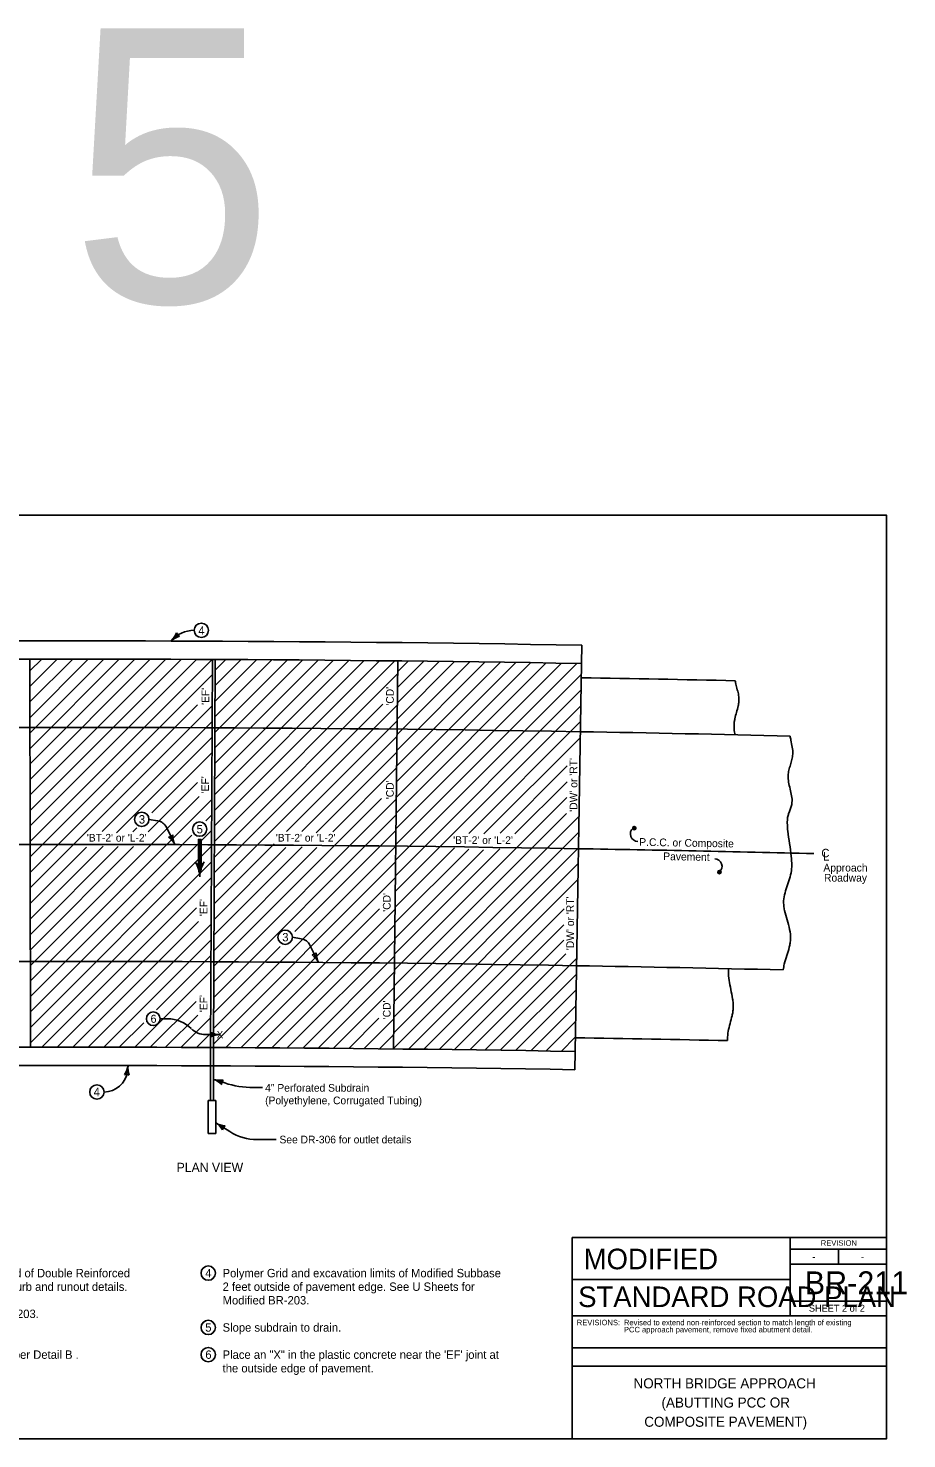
# Model space of a CAD drawing. Extents: x 10130 to 81668, y 5440 to 21644.
# Drawn here: x 25789 to 27712, y 7924 to 11009 of the extents above; entities that cross this region are included whole.
import ezdxf

# ---------------------------------------------------------------- set-up
doc = ezdxf.new("R2010")
doc.units = 0
for name, color, linetype in [('Default', 7, 'Continuous'), ('dsnStdBlockModified', 7, 'Continuous'), ('dsnStdBlockNotModified', 7, 'Continuous'), ('dsnStdBorder', 7, 'Continuous'), ('dsnStdLabel', 7, 'Continuous'), ('dsnstdModifiedBlock', 7, 'Continuous'), ('Level 1', 7, 'Continuous'), ('SheetBorder', 7, 'Continuous'), ('SheetText', 7, 'Continuous')]:
    doc.layers.add(name, color=color, linetype=linetype)

msp = doc.modelspace()

# ---------------------------------------------------------------- linework, layer by layer
at = {"layer": 'Default'}
for p, q in [((27000.2, 9619.8), (27000.8, 9659.8)), ((26985.7, 8771.3), (26985.1, 8731.3))]:
    msp.add_line(p, q, dxfattribs=at)
for radius, end in [(65123.7, 90.60898), (64195, 90.563142)]:
    msp.add_arc((25894.2, -55454.5), radius, 89.026299, end, dxfattribs=at)
for points in [[(27336.5, 9582), (27337.1, 9577.8), (27340.1, 9565.4), (27343.2, 9553.1), (27344.3, 9547), (27344.5, 9543.9), (27344.5, 9540.8), (27344.1, 9533.7), (27342.8, 9526.8), (27339.2, 9512.8), (27335.5, 9498.8), (27334.2, 9491.8), (27333.8, 9488.3), (27333.7, 9484.7), (27334.8, 9469.7), (27335.9, 9463.9)], [(27456.5, 9461.1), (27458.3, 9451.8), (27461.2, 9436.7), (27462.2, 9421.6), (27460.5, 9409.8), (27457.2, 9398.1), (27453.9, 9386.4), (27452.1, 9374.7), (27453.2, 9360), (27456.4, 9345.2), (27459.7, 9330.4), (27460.6, 9315.7), (27458.9, 9306.8), (27455.7, 9298.1), (27452.6, 9289.4), (27450.7, 9280.5), (27450.5, 9267), (27451.4, 9253.3), (27455.2, 9225.8), (27459, 9198.3), (27460.1, 9177.9), (27459.8, 9171.1), (27456.6, 9153.4), (27451, 9135.8), (27445.4, 9118.3), (27442.3, 9100.6), (27442.6, 9090.2), (27444.2, 9079.7), (27449.8, 9058.9), (27455.4, 9038.1), (27457.6, 9017.4), (27456.6, 9008.2), (27454.7, 8999), (27449.2, 8980.7), (27443.7, 8962.3), (27441.4, 8949.5)], [(27321.7, 8952.3), (27321.4, 8946.6), (27322.9, 8926.7), (27326.8, 8906.6), (27330.5, 8886.5), (27331.3, 8881.6), (27331.8, 8876.6), (27331.9, 8871.6), (27331.8, 8866.6), (27331.1, 8857.9), (27329.5, 8849.4), (27325.2, 8832.3), (27321.1, 8815.2), (27319.5, 8797.9), (27319.6, 8794.8)]]:
    msp.add_spline(points, degree=3, dxfattribs=at)
at = {"layer": 'dsnStdBlockModified'}
for p, q in [((26053.1, 9278.8), (26072.6, 9275.5)), ((26091.4, 9261.5), (26110.1, 9223.7)), ((26367.1, 9021), (26386.6, 9017.8)), ((26405.4, 9003.8), (26424, 8965.9)), ((26093.9, 8842.6), (26077.6, 8842.6)), ((26208.4, 8808), (26177.2, 8808)), ((26005.9, 8727.4), (26007.6, 8740.5)), ((26301.6, 8692.3), (26282, 8692.3)), ((26230.1, 8595.8), (26199.5, 8614.9)), ((26331.7, 8578.5), (26290.1, 8578.5))]:
    msp.add_line(p, q, dxfattribs=at)
for centre, radius, start, end in [((26152.2, 9625.5), 66.8, 90, 139.4393), ((26068.4, 9250.2), 25.7, 26.2458, 80.4677), ((27123.4, 9247.1), 16.5, 130.2796, 268.9704), ((27291.1, 9176.2), 16.5, 310.2794, 88.9704), ((26382.3, 8992.4), 25.7, 26.2458, 80.4677), ((26093.9, 8769.2), 73.4, 45, 90), ((26177.2, 8852.1), 44.1, 225, 270), ((25954.9, 8733.9), 51.4, 270, 352.7713), ((26282, 8897.9), 205.6, 252.1406, 270), ((26290.1, 8691.6), 113.1, 237.9168, 270)]:
    msp.add_arc(centre, radius, start, end, dxfattribs=at)
at = {"layer": 'dsnStdBorder'}
for p, q in [((25792.7, 9603.4), (25818.6, 9629.2)), ((25792.8, 9535.6), (25886.5, 9629.2)), ((25792.8, 9569.5), (25852.5, 9629.2)), ((25792.9, 9501.7), (25920.4, 9629.2)), ((25793, 9433.9), (25988.2, 9629.2)), ((25793, 9467.8), (25954.3, 9629.2)), ((25793.1, 9400), (26022.1, 9629.1)), ((25793.1, 9366.2), (26056, 9629)), ((25793.2, 9332.3), (26089.8, 9628.9)), ((25793.2, 9298.4), (26123.7, 9628.8)), ((25793.3, 9264.5), (26157.5, 9628.7)), ((25793.3, 9230.6), (26191.3, 9628.6)), ((26196.6, 9264.4), (26558, 9625.9)), ((26196.8, 9298.5), (26524.4, 9626.2)), ((26196.9, 9332.6), (26490.8, 9626.5)), ((26197.1, 9366.7), (26457.2, 9626.8)), ((26197.2, 9400.8), (26423.5, 9627.1)), ((26197.4, 9434.9), (26389.8, 9627.4)), ((26197.5, 9469), (26356.1, 9627.6)), ((26197.7, 9503.1), (26322.4, 9627.8)), ((26197.9, 9537.2), (26288.7, 9628)), ((26198, 9571.3), (26255, 9628.2)), ((26198.2, 9605.4), (26221.2, 9628.4)), ((25793.4, 9196.7), (26192, 9595.3)), ((26196.3, 9196.2), (26597.4, 9597.3)), ((26196.4, 9230.3), (26591.6, 9625.5)), ((26593, 9189.5), (26999.8, 9596.3)), ((26593.4, 9223.8), (26989.5, 9620)), ((26593.7, 9258.2), (26956.1, 9620.6)), ((26594.1, 9292.5), (26922.7, 9621.1)), ((26594.5, 9326.8), (26889.3, 9621.6)), ((26594.8, 9361.1), (26855.9, 9622.1)), ((26595.2, 9395.4), (26822.4, 9622.6)), ((26595.6, 9429.7), (26789, 9623.1)), ((26596, 9464), (26755.5, 9623.5)), ((26596.3, 9498.3), (26722, 9624)), ((26596.7, 9532.7), (26688.4, 9624.4)), ((26597.1, 9567), (26654.9, 9624.8)), ((26597.4, 9601.3), (26621.3, 9625.2)), ((26592.6, 9155.2), (26999.2, 9561.8)), ((25793.4, 9162.8), (26159.6, 9529)), ((25793.5, 9128.9), (26191.6, 9527.1)), ((26196, 9128), (26596.7, 9528.7)), ((26196.1, 9162.1), (26565, 9531)), ((26592.2, 9120.9), (26998.6, 9527.3)), ((25950.6, 9252.2), (26191.5, 9493)), ((26354, 9252.1), (26596.3, 9494.4)), ((26753.5, 9248.2), (26998, 9492.7)), ((25981.8, 9249.4), (26191.3, 9458.9)), ((26388, 9252.1), (26595.9, 9460.1)), ((26786.1, 9246.9), (26997.4, 9458.2)), ((26059.4, 9293.1), (26191.2, 9424.8)), ((26419.3, 9249.5), (26595.5, 9425.8)), ((26455.3, 9251.6), (26595.2, 9391.5)), ((26821.8, 9248.6), (26968.8, 9395.6)), ((26051.8, 9251.5), (26159.5, 9359.2)), ((26854.2, 9247.1), (26968.3, 9361.2)), ((25793.7, 8959.5), (26162.8, 9328.6)), ((25793.8, 8925.6), (26190.7, 9322.5)), ((26195, 8923.4), (26594.4, 9322.8)), ((26195.2, 8957.5), (26562.5, 9324.8)), ((26590.4, 8949.4), (26967.5, 9326.4)), ((26177.9, 9275.8), (26190.5, 9288.4)), ((26194.9, 8889.3), (26594.1, 9288.5)), ((26590, 8915), (26966.9, 9291.9)), ((26018.1, 9251.7), (26026.4, 9260.1)), ((26589.6, 8880.7), (26994.5, 9285.6)), ((25793.8, 8891.7), (26146.7, 9244.6)), ((25793.9, 8857.8), (26190.4, 9254.3)), ((26164.4, 9180.6), (26164.4, 9235.1)), ((26195.8, 9093.9), (26327, 9225.1)), ((26372.8, 9033.3), (26593.7, 9254.2)), ((26589.3, 8846.4), (26993.9, 9251)), ((25793.5, 9095.1), (25916.7, 9218.2)), ((25793.6, 9061.2), (25952.9, 9220.4)), ((25793.6, 9027.3), (25985.5, 9219.1)), ((25793.7, 8993.4), (26019.4, 9219.1)), ((25794, 8823.9), (26190.2, 9220.2)), ((26194.5, 8821.1), (26593.3, 9219.9)), ((26195.3, 8991.6), (26420.7, 9217)), ((26195.5, 9025.7), (26388.2, 9218.4)), ((26195.6, 9059.8), (26352.8, 9217)), ((26588.9, 8812.1), (26993.3, 9216.5)), ((26590.8, 8983.7), (26821.2, 9214.1)), ((26591.1, 9018), (26785.4, 9212.3)), ((26591.5, 9052.3), (26753.1, 9213.8)), ((26591.9, 9086.6), (26721.7, 9216.4)), ((25794, 8790.1), (26190.1, 9186.1)), ((26161.3, 9180.7), (26161.3, 9180.7)), ((26167.7, 9180.8), (26167.7, 9180.8)), ((26194.4, 8787), (26592.9, 9185.6)), ((26588.5, 8777.8), (26992.7, 9182)), ((25818.4, 8780.5), (26189.9, 9152)), ((26221.1, 8779.8), (26592.6, 9151.3)), ((26621.2, 8776.5), (26992.1, 9147.5)), ((25852.4, 8780.6), (26157.2, 9085.4)), ((26254.8, 8779.6), (26558.1, 9082.8)), ((26288.6, 8779.4), (26591.8, 9082.6)), ((26654.7, 8776.1), (26961.7, 9083.1)), ((25886.4, 8780.6), (26161.5, 9055.7)), ((25920.3, 8780.6), (26189.4, 9049.7)), ((26322.3, 8779.2), (26591.5, 9048.3)), ((26688.2, 8775.7), (26960.9, 9048.3)), ((25954.2, 8780.6), (26189.3, 9015.6)), ((26356, 8778.9), (26591.1, 9014)), ((26721.8, 8775.3), (26961.3, 9014.8)), ((26069.5, 8861.9), (26189.1, 8981.5)), ((26194.7, 8855.2), (26340.1, 9000.6)), ((26389.7, 8778.7), (26590.7, 8979.7)), ((26755.3, 8774.8), (26965.3, 8984.9)), ((26022, 8780.5), (26189, 8947.4)), ((26788.7, 8774.4), (26989.2, 8974.8)), ((26423.4, 8778.4), (26590.3, 8945.4)), ((26822.2, 8773.9), (26988.6, 8940.3)), ((26457, 8778.1), (26590, 8911.1)), ((26855.7, 8773.4), (26988, 8905.8)), ((26055.9, 8780.4), (26156.2, 8880.7)), ((26889.1, 8772.9), (26987.4, 8871.2)), ((25988.1, 8780.5), (26041.7, 8834.1)), ((26089.7, 8780.3), (26160, 8850.6)), ((26123.5, 8780.2), (26188.5, 8845.1)), ((26490.6, 8777.8), (26556.6, 8843.8)), ((26524.3, 8777.5), (26589.2, 8842.5)), ((26922.5, 8772.4), (26986.9, 8836.7)), ((26157.3, 8780), (26188.3, 8811)), ((26557.9, 8777.2), (26588.9, 8808.1)), ((26955.9, 8771.8), (26986.3, 8802.2)), ((26188.2, 8779.9), (26188.2, 8664.2)), ((26194.4, 8779.9), (26194.4, 8664.2)), ((26218.9, 8702.2), (26194.4, 8710.2)), ((26194.4, 8710.2), (26213.2, 8704.1)), ((26183, 8664.2), (26199.5, 8664.2)), ((26183, 8664.2), (26183, 8591.8)), ((26199.5, 8664.2), (26199.5, 8591.8)), ((26199.5, 8614.9), (26216.2, 8604.4)), ((26183, 8591.8), (26199.5, 8591.8))]:
    msp.add_line(p, q, dxfattribs=at)
msp.add_lwpolyline([(24968.4, 9591.4), (25065.1, 9592.8), (25143.6, 9606.4), (25183, 9607), (25202.6, 9610.6), (25202.4, 9625.6), (25553.2, 9628.3), (25792.7, 9629.2), (25794, 8780.5), (25396.8, 8778.7), (25262.8, 8777.5), (25262.8, 8777.5), (25262.6, 8792.5), (25242.9, 8795.5), (25203.5, 8794.9), (25124.6, 8806.2), (25027.9, 8804.9)], close=True, dxfattribs=at)
for points in [[(27115.1, 9256.4), (27116.4, 9256.9), (27118.3, 9257.4), (27118.7, 9259.3), (27118.5, 9261), (27117.3, 9262.6), (27115.5, 9262.5), (27113.6, 9262.3), (27112.6, 9260.8), (27112.4, 9259.2), (27113.5, 9257.1), (27114.9, 9256.9), (27116.8, 9257.3), (27118.4, 9258.5), (27118.4, 9260.3), (27117.2, 9261.8), (27115.5, 9262), (27113.6, 9261.6), (27113.2, 9260.6), (27112.8, 9259.3), (27113.7, 9257.7), (27115.1, 9257.7), (27116.7, 9257.9), (27117.8, 9258.8), (27117.3, 9260.4), (27116.1, 9261.3), (27114.5, 9261.4), (27114.1, 9260.6), (27113.6, 9259.6), (27114.3, 9258.3), (27115.5, 9258), (27116.6, 9258.6), (27116.7, 9259.8), (27116.1, 9260.6), (27115.1, 9260.9), (27114.5, 9260.5), (27114.2, 9259.8), (27114.8, 9258.9), (27115.5, 9258.7), (27116.2, 9259.1), (27116.1, 9259.8), (27115.6, 9260.2), (27114.9, 9260.2), (27114.9, 9259.6), (27115.5, 9259.3)], [(26167.4, 9180.7), (26167.4, 9235.1), (26161.3, 9235.1), (26161.3, 9180.7), (26166.6, 9180.9), (26166.8, 9234.4), (26161.9, 9234.3), (26162.1, 9181.9), (26165.7, 9181.8), (26165.9, 9233.7), (26162.7, 9233.5), (26162.7, 9182.6), (26165, 9182.4), (26165.3, 9233.1), (26163.4, 9233), (26163.5, 9183.3)], [(26171.5, 9182.2), (26167.8, 9179.8), (26162.4, 9179.6), (26157.7, 9181.6), (26161, 9173.5), (26163.8, 9164.1), (26164.4, 9161.5), (26165.7, 9168.3), (26169.1, 9178.1), (26170.7, 9181.1), (26159.3, 9180), (26164.2, 9165.5), (26168.5, 9179.6), (26160.6, 9179.1), (26164.2, 9169.1), (26166.5, 9178.3), (26161.9, 9178.7), (26164, 9172.4), (26165.3, 9177.2), (26163.1, 9177.5), (26163.8, 9175.1)], [(27301.4, 9160.3), (27302.7, 9160.8), (27304.6, 9161.3), (27305, 9163.3), (27304.7, 9165), (27303.6, 9166.5), (27301.8, 9166.4), (27299.8, 9166.2), (27298.9, 9164.7), (27298.7, 9163.1), (27299.8, 9161), (27301.2, 9160.8), (27303.1, 9161.2), (27304.7, 9162.4), (27304.6, 9164.2), (27303.5, 9165.7), (27301.8, 9165.9), (27299.8, 9165.5), (27299.5, 9164.5), (27299.1, 9163.2), (27300, 9161.6), (27301.4, 9161.6), (27303, 9161.9), (27304.1, 9162.7), (27303.6, 9164.3), (27302.4, 9165.3), (27300.8, 9165.3), (27300.4, 9164.5), (27299.9, 9163.5), (27300.6, 9162.3), (27301.8, 9162), (27302.9, 9162.5), (27302.9, 9163.7), (27302.4, 9164.5), (27301.3, 9164.8), (27300.8, 9164.4), (27300.5, 9163.7), (27301, 9162.8), (27301.8, 9162.6), (27302.5, 9163), (27302.4, 9163.7), (27301.9, 9164.1), (27301.1, 9164.1), (27301.1, 9163.5), (27301.8, 9163.2)], [(26213.9, 8707.7), (26212.1, 8704.4), (26211.7, 8700.7), (26208.1, 8704.1), (26201.9, 8707.7), (26209.6, 8707.1), (26213.2, 8707.5), (26211.4, 8704.6), (26211, 8702.3), (26208.6, 8704.5), (26205.2, 8706.6), (26209.5, 8706.5), (26211.8, 8706.6), (26210.5, 8703.7), (26208.1, 8705.7), (26210.5, 8705.7), (26210.2, 8704.6), (26209.3, 8705.3)], [(26217.8, 8607.8), (26215.3, 8605), (26213.9, 8601.5), (26211.3, 8605.6), (26206.2, 8610.7), (26213.5, 8608.2), (26217.1, 8607.7), (26214.7, 8605.4), (26213.7, 8603.2), (26212, 8605.9), (26209.2, 8608.9), (26213.3, 8607.7), (26215.6, 8607.2), (26213.5, 8604.7), (26211.7, 8607.2), (26214, 8606.6), (26213.5, 8605.7), (26212.8, 8606.6)]]:
    msp.add_lwpolyline(points, dxfattribs=at)
for centre, radius in [((26167.9, 9692.3), 15.7), ((26037.4, 9278.8), 15.7), ((26164.1, 9257.4), 15.7), ((27115.5, 9259.7), 3.62), ((27301.8, 9163.6), 3.62), ((26351.3, 9021), 15.7), ((26062.5, 8842.6), 15), ((25939.2, 8682.5), 15.7), ((26182.9, 8286.4), 15.7), ((26182.9, 8167.5), 15.7), ((26182.9, 8108.1), 15.7)]:
    msp.add_circle(centre, radius, dxfattribs=at)
for centre, radius, start, end in [((26071.3, 9701.5), 44.4, 312.7719, 340.8444), ((26131.6, 9636.3), 44.4, 104.6994, 132.7719), ((26128.8, 9694.2), 17.1, 205.0386, 240.5053), ((25894.2, -55454.5), 64934.4, 89.026299, 90.808989), ((26093.6, 9257), 17.1, 278.5122, 313.9789), ((26070.3, 9204), 44.4, 26.2455, 54.318), ((26149.9, 9243.3), 44.4, 178.1731, 206.2455), ((25894.2, -55454.5), 64678.5, 88.569913, 89.026299), ((26164.4, 9191.9), 11.6, 211.7147, 328.2853), ((26098.1, 9150.9), 66.3, 1.6842, 31.7143), ((26230.6, 9150.9), 66.3, 148.2857, 178.3158), ((26407.6, 8999.3), 17.1, 278.5122, 313.9789), ((26384.2, 8946.3), 44.4, 26.2455, 54.318), ((26463.8, 8985.6), 44.4, 178.1731, 206.2455), ((25894.2, -55454.5), 64422.6, 89.026299, 90.781002), ((26173, 8808), 16.3, 342.2666, 17.7333), ((26208.4, 8850.3), 42.3, 241.9275, 270), ((26208.4, 8765.7), 42.3, 90, 118.0725), ((25963.5, 8746.1), 44.4, 324.6988, 352.7713), ((26051.6, 8734.9), 44.4, 172.7713, 200.8438), ((26002.9, 8703.6), 17.1, 65.0379, 100.5046), ((26181, 8668.6), 43.7, 44.0691, 72.1415), ((26207.8, 8751.7), 43.7, 252.1415, 280.214), ((26229.2, 8698.9), 16.9, 144.4082, 179.8749), ((26176.3, 8577.9), 43.7, 29.8434, 57.9159), ((26222.7, 8652), 43.7, 237.9159, 265.9884), ((26230.5, 8595.5), 16.9, 130.1825, 165.6492)]:
    msp.add_arc(centre, radius, start, end, dxfattribs=at)
at = {"layer": 'dsnStdLabel'}
for p, q in [((27456.6, 8364), (27456.6, 8272.7)), ((27456.6, 8339.1), (27667.5, 8339.1)), ((27562.1, 8339.1), (27562.1, 8305.9)), ((27456.6, 8305.9), (27667.5, 8305.9)), ((26979.5, 8272.7), (27456.6, 8272.7)), ((27456.6, 8272.7), (27456.6, 8192.7)), ((27667.5, 8224.9), (27456.6, 8224.9)), ((26979.5, 8192.7), (27667.5, 8192.7)), ((26979.5, 8122.7), (27667.5, 8122.7)), ((26979.5, 8082.7), (27667.5, 8082.7)), ((26979.5, 8082.7), (27667.5, 8082.7))]:
    msp.add_line(p, q, dxfattribs=at)
msp.add_lwpolyline([(26979.5, 8364), (27667.5, 8364), (27667.5, 7924), (26979.5, 7924)], close=True, dxfattribs=at)
at = {"layer": 'dsnstdModifiedBlock'}
for p, q in [((25794, 8780.5), (25792.7, 9629.2)), ((26188.2, 8779.9), (26192.1, 9628.6)), ((26194.4, 8779.9), (26198.3, 9628.5)), ((26588.5, 8776.8), (26597.7, 9625.4)), ((26985.7, 8771.3), (27000.2, 9619.8))]:
    msp.add_line(p, q, dxfattribs=at)
for radius, start, end in [(65083.7, 89.026299, 90.60898), (65052.5, 88.729583, 89.026299), (64934.4, 88.621312, 89.026299), (64678.5, 89.026299, 90.795051), (64422.6, 88.623824, 89.026299), (64265.1, 88.729039, 89.026299), (64235, 89.026299, 90.563142)]:
    msp.add_arc((25894.2, -55454.5), radius, start, end, dxfattribs=at)
at = {"layer": 'SheetBorder'}
msp.add_lwpolyline([(24532.5, 9944), (27667.5, 9944), (27667.5, 7924), (24532.5, 7924)], close=True, dxfattribs=at)

# ---------------------------------------------------------------- texts
at = {"layer": 'dsnStdBlockModified'}
for s, height, p in [('4', 18.4, (26161.2, 9682.5)), ('3', 18.4, (26031, 9269.6)), ('5', 18.4, (26157.5, 9248.2)), ("'BT-2' or 'L-2'", 16.8, (25917.2, 9230.2)), ("'BT-2' or 'L-2'", 16.8, (26330.8, 9230.2)), ("'BT-2' or 'L-2'", 16.8, (26719, 9225)), ('C', 18.5, (27524.8, 9195.8)), ('L', 18.5, (27528.7, 9188.7)), ('Approach', 16.88, (27529.3, 9164.7)), ('Roadway', 16.88, (27530.7, 9142.7)), ('3', 18.4, (26344.9, 9011.9)), ('6', 17.5, (26056.7, 8833.9)), ('X', 16, (26201.5, 8800)), ('4" Perforated Subdrain ', 16.8, (26307.5, 8683.2)), ('4', 18.4, (25932.1, 8673.3)), ('(Polyethylene, Corrugated Tubing)', 16.8, (26307.5, 8655.7)), ('See DR-306 for outlet details', 16.8, (26338.9, 8570.1)), ('Build 4 inch Sloped Curb to end of Double Reinforced', 18.375, (25428.4, 8277.2)), ('4', 18.4, (26176.4, 8277.2)), ('Polymer Grid and excavation limits of Modified Subbase', 18.375, (26214.4, 8277.2)), ('Section.  Refer to PV-102 for curb and runout details.', 18.375, (25428.4, 8247.5)), ('2 feet outside of pavement edge. See U Sheets for', 18.375, (26214.4, 8247.5)), ('See U Sheets for Modified BR-203.', 18.375, (25428.4, 8188.1)), ('Modified BR-203.', 18.375, (26214.4, 8217.8)), ('5', 18.4, (26176.4, 8158.3)), ('Slope subdrain to drain.', 18.375, (26214.4, 8158.3)), ('     Single Pour - Saw cut joint per Detail B .', 18.375, (25428.4, 8098.9)), ('6', 18.4, (26176.6, 8098.9)), ('Place an "X" in the plastic concrete near the \'EF\' joint at', 18.375, (26214.4, 8098.9)), ('the outside edge of pavement.', 18.375, (26214.4, 8069.2))]:
    msp.add_text(s, height=height, dxfattribs=at).set_placement(p)
for s, height, rotation, p in [("'EF'", 16.8, 90, (26185, 9529.2)), ("'CD'", 16.8, 90, (26589, 9527.5)), ("'DW' or 'RT'", 16.884, 90, (26990.8, 9295.4)), ("'EF'", 16.8, 90, (26184.6, 9335.8)), ("'CD'", 16.8, 90, (26589, 9323)), ('P.C.C. or Composite', 16.884, 358.9704, (27126.1, 9221)), ('Pavement', 16.88, 358.9704, (27178.6, 9189.7)), ("'EF'", 16.8, 90, (26181, 9067.2)), ("'CD'", 16.8, 90, (26582, 9076.7)), ("'DW' or 'RT'", 16.884, 90, (26983.5, 8992.6)), ("'EF'", 16.8, 90, (26181, 8857.2)), ("'CD'", 16.8, 90, (26582, 8841.5))]:
    msp.add_text(s, height=height, rotation=rotation, dxfattribs=at).set_placement(p)
at = {"layer": 'dsnStdBlockNotModified'}
msp.add_text('PLAN VIEW', height=20, dxfattribs=at).set_placement((26113.7, 8507.6))
at = {"layer": 'dsnStdLabel'}
for s, height, p in [('REVISION', 12, (27523.6, 8346.2)), ('-', 15, (27505.1, 8314.7)), ('-', 15, (27611.6, 8315.1)), ('BR-211', 50, (27488.4, 8240.2)), ('STANDARD ROAD PLAN', 45.001, (26992.6, 8212.1)), ('SHEET 2 of 2', 15, (27497.6, 8202)), ('Revised to extend non-reinforced section to match length of existing ', 12, (27092.8, 8172.3)), ('PCC approach pavement, remove fixed abutment detail.', 12, (27092.8, 8156.8)), ('NORTH BRIDGE APPROACH', 22, (27113.8, 8034.3)), ('(ABUTTING PCC OR', 22, (27175, 7992.3)), ('COMPOSITE PAVEMENT)', 22, (27137.3, 7950.3))]:
    msp.add_text(s, height=height, dxfattribs=at).set_placement(p)
at = {"layer": 'Level 1'}
for s, height, p in [('MODIFIED', 45, (27004.6, 8294.8)), ('REVISIONS:', 12, (26989.5, 8172.3))]:
    msp.add_text(s, height=height, dxfattribs=at).set_placement(p)
at = {"layer": 'SheetText'}
msp.add_text('5', height=600, dxfattribs=at).set_placement((25880.7, 10409.2))

doc.saveas('drawing.dxf')
